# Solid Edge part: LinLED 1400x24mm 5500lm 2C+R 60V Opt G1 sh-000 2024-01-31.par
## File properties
Author: robert.pupel
Template: iso metric part.par
Last saved by: robert.pupel
Revision: 3
Application: Solid Edge
Gęstość: 0.000 kg/m^3
Dokładność: 0.990
Username: robert.pupel
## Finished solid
Body 1: solid body, 3817 faces, 9922 edges, 6492 vertices.
  Faces by surface: plane 3174, cylinder 327, torus 128, cone 100, spline 52, sphere 32, swept 4
  Edges by curve: line 8452, curve on surface 752, circle 418, spline 168, ellipse 132
Bounding box of the edges (mm; curved faces can reach further): 1399.600 x 4.450 x 24.000, from (-559.8, -3.45, -12) to (839.8, 1, 12).
Cylindrical faces by radius (mm): R0.2 x92, R0.2169 x12, R0.25 x54, R0.3373 x12, R0.4 x16, R0.4006 x4, R0.4008 x4, R0.525 x4, R0.6 x40, R1 x20, R1.1 x8, R1.1989 x4, R1.199 x4, R1.2 x20, R1.5309 x2, R1.5312 x2, R1.7414 x2, R1.7423 x2, R2.15 x25
Conical faces (half-angle, radius in mm at the cone's reference point): 0.398 deg R1.1964 x4, 0.4493 deg R1.1964 x4, 0.4746 deg R1.1948 x4, 0.4758 deg R1.1948 x4, 0.5 deg R0.5056 x8, 0.5 deg R1.0082 x8, 1 deg R0.5511 x4, 10 deg R0.2132 x8, 10 deg R0.4132 x8, 16.0099 deg R1.1053 x4, 16.1249 deg R1.1279 x4, 18.8604 deg R1.0669 x8, 19.5041 deg R0.5138 x4, 19.8244 deg R0.5099 x4, 27.363 deg R0.6214 x4, 40.6434 deg R0.5161 x4, 43.3309 deg R0.4892 x4, 45 deg R0.575 x4, 45 deg R0.625 x8
Toroidal faces (ring radius, tube radius in mm): R0.0958 r0.3997 x8, R0.1076 r0.4 x4, R0.1101 r0.4001 x4, R0.1217 r0.4 x4, R0.1234 r0.4 x4, R0.1626 r0.228 x4, R0.1634 r0.2287 x4, R0.3287 r0.2001 x4, R0.3684 r0.2151 x4, R0.3703 r0.4 x4, R0.3818 r0.2 x8, R0.4166 r0.3983 x4, R0.5981 r0.197 x4, R0.5982 r0.197 x4, R0.6009 r0.3968 x4, R0.6009 r0.3969 x4, R0.6227 r0.2 x4, R0.6235 r0.2 x4, R0.8 r0.2 x8, R0.8522 r0.3 x4, R0.9002 r0.2 x4, R0.9018 r0.2 x4, R0.9197 r0.223 x4, R0.9365 r0.2 x4, R0.9663 r0.2263 x4, R0.9665 r0.2263 x4, R1.429 r1.2 x4, R1.8741 r0.2175 x4, R1.9007 r0.2 x4
Spherical faces by radius (mm): R0.2 x24, R0.6 x8
Planar faces by outward normal: +x 383, +y 17, +z 407, -x 383, -y 566, -z 422, oblique 996
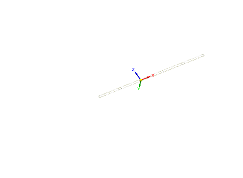
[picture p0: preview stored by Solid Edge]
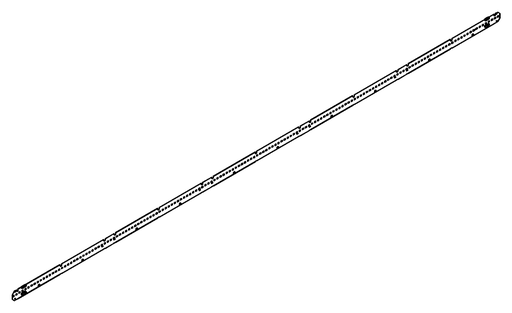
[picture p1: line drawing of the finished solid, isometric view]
